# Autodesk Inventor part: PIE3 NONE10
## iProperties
Shininess: 64.0
Length Units: 11269
Angle Units: 11279
Time Units: 11290
Mass Units: 11286
Length Display Precision: 3
Angle Display Precision: 2
Compacted: True
Part Number: PIE3 NONE10
Document SubType Name: Modeling
Created: 2004-08
Designer: John Blackburn
Manufacturer: Standard
Standards Organization: Custom
Density: 0.0
Volumn: 0.0
Area: 0.0
PropertySet Name: Model Information
Control State: 0
Master: False
Checked Out: False
Author: John Blackburn
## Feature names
1. Erst1
